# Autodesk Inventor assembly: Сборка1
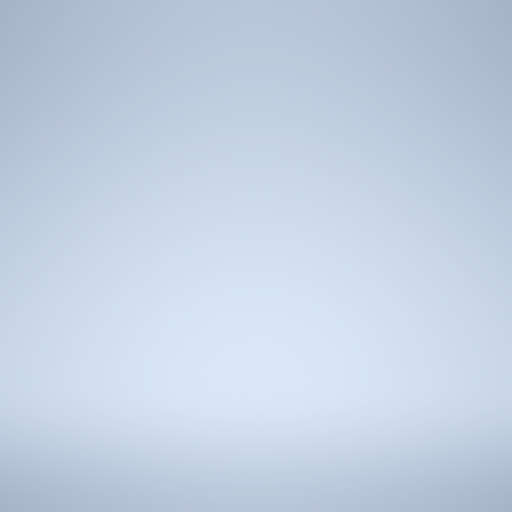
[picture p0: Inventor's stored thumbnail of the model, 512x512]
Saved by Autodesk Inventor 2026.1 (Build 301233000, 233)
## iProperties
Created: 2026-01
Part Number: Сборка1
Document SubType Name: Assembly
Designer: Yury Melnikov
Author: Yury Melnikov
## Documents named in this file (1)
- C:\Users\user\Documents\Проекты\ВсОШ_РОБО\Робот\Сборка1.iam
